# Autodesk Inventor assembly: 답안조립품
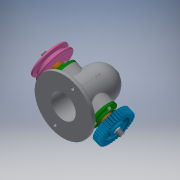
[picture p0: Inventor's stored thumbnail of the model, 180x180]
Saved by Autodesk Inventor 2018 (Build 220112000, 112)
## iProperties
Created: 2019-11
Part Number: 답안조립품
Document SubType Name: Assembly
Designer: Administrator
Author: Administrator
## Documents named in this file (12)
- C:\Users\Administrator\Desktop\491104V1059\답안조립품.iam
- C:\Users\Administrator\Desktop\491104V1059\본체.ipt
- C:\Users\Administrator\Desktop\491104V1059\축.ipt
- C:\Users\Administrator\Desktop\491104V1059\베어링 6203.ipt
- C:\Users\Administrator\Desktop\491104V1059\커버.ipt
- C:\Users\Administrator\Desktop\491104V1059\볼트 M4.ipt
- C:\Users\Administrator\Desktop\491104V1059\오일 실 26 38 8.ipt
- C:\Users\Administrator\Desktop\491104V1059\부시.ipt
- C:\Users\Administrator\Desktop\491104V1059\키 5x5x12.ipt
- C:\Users\Administrator\Desktop\491104V1059\V-벨트풀리.ipt
- V-벨트풀리.ipt
- C:\Users\Administrator\Desktop\491104V1059\스퍼기어.ipt
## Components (1 placed, 1 different names)
1. V-벨트풀리:1
